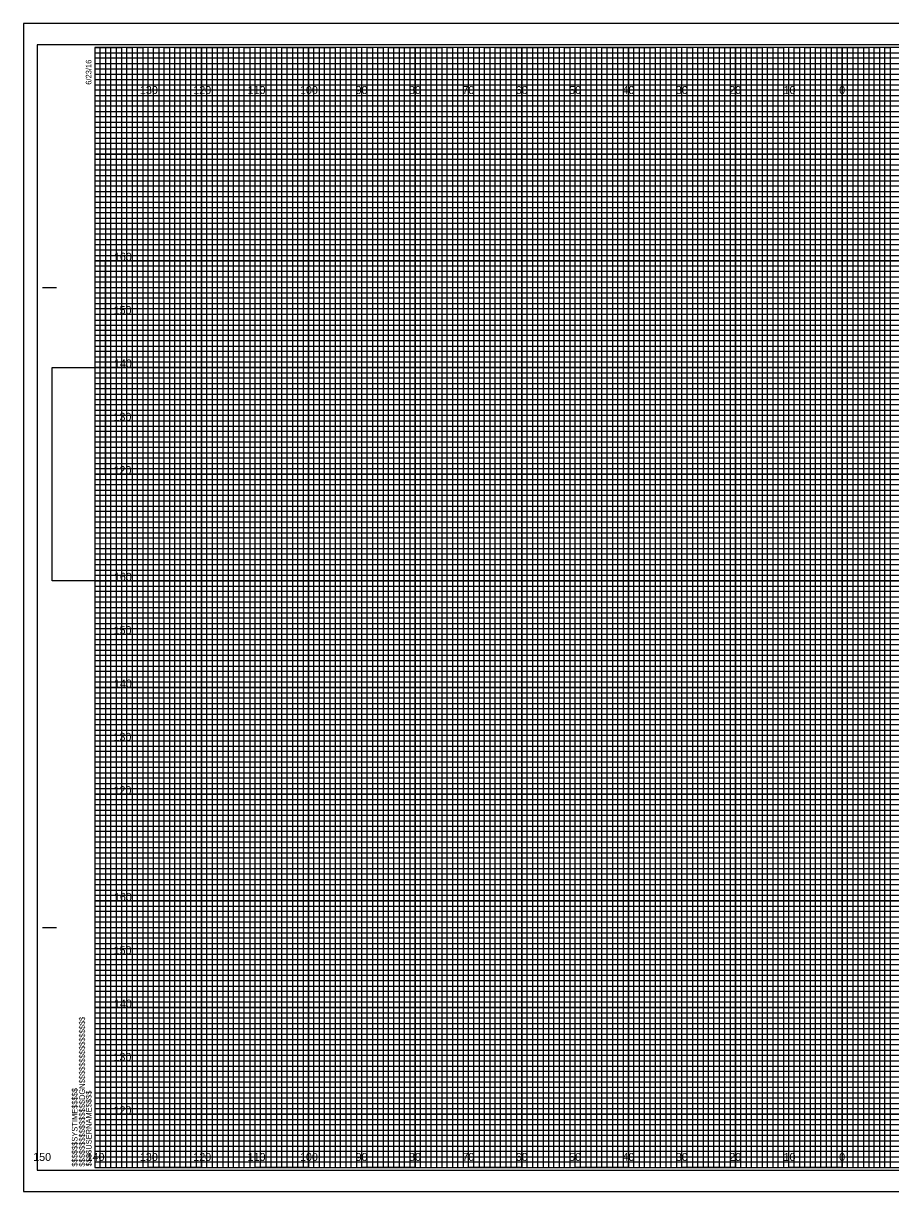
# Model space of a CAD drawing. Extents: x -13 to 323, y -5 to 3294.
# Drawn here: x -13.4 to 149.1, y 1095.5 to 1314.5 of the extents above; entities that cross this region are included whole.
import ezdxf

# ---------------------------------------------------------------- set-up
doc = ezdxf.new("R2010")
doc.units = 0
for name, color, linetype in [('Prop XS Elevation Labels', 7, 'Continuous'), ('Prop XS Offset Labels', 7, 'Continuous'), ('Scratch_Level_0', 7, 'Continuous'), ('Sheet Cross Section CELL', 7, 'Continuous'), ('Sheet Cross Section Grid Major CELL', 7, 'Continuous'), ('Sheet Cross Section Grid Middle CELL', 7, 'Continuous'), ('Sheet Cross Section Grid Minor 1 CELL', 7, 'Continuous'), ('Sheet Cross Section Grid Minor 2 CELL', 7, 'Continuous'), ('Sheet Cutting Line CELL', 7, 'Continuous'), ('Sheet DOT Grid CELL', 7, 'Continuous'), ('Sheet Plot Border Inside CELL', 7, 'Continuous'), ('Sheet Plot Border Outside CELL', 7, 'Continuous')]:
    doc.layers.add(name, color=color, linetype=linetype)

msp = doc.modelspace()

# ---------------------------------------------------------------- linework, layer by layer
at = {"layer": 'Scratch_Level_0'}
for points in [[(2, 1270), (310, 1270), (310, 1230), (2, 1230)], [(-8, 1250), (300, 1250), (300, 1210), (-8, 1210)], [(10, 1210), (310, 1210), (310, 1170), (10, 1170)], [(10, 1150), (310, 1150), (310, 1110), (10, 1110)]]:
    msp.add_lwpolyline(points, close=True, dxfattribs=at)
at = {"layer": 'Sheet Cross Section CELL'}
for p, q in [((-9.8, 1265), (-7.3, 1265)), ((-9.7, 1265), (-7.2, 1265)), ((-9.8, 1145), (-7.3, 1145)), ((-9.7, 1145), (-7.2, 1145)), ((0, 1100), (0, 1100)), ((0, 1100), (0, 1100)), ((0, 1100), (0, 1100)), ((0, 1100), (0, 1100)), ((0, 1100), (0, 1100)), ((0, 1100), (0, 1100)), ((0, 1100), (0, 1100))]:
    msp.add_line(p, q, dxfattribs=at)
msp.add_lwpolyline([(320, 1310), (0, 1310), (0, 1100), (320, 1100)], close=True, dxfattribs=at)
at = {"layer": 'Sheet Cross Section Grid Major CELL'}
for p, q in [((10, 1310), (0, 1310)), ((10, 1100), (10, 1310)), ((30, 1310), (20, 1310)), ((20, 1310), (20, 1100)), ((30, 1100), (30, 1310)), ((50, 1310), (40, 1310)), ((40, 1310), (40, 1100)), ((50, 1100), (50, 1310)), ((70, 1310), (60, 1310)), ((60, 1310), (60, 1100)), ((70, 1100), (70, 1310)), ((90, 1310), (80, 1310)), ((80, 1310), (80, 1100)), ((90, 1100), (90, 1310)), ((110, 1310), (100, 1310)), ((100, 1310), (100, 1100)), ((110, 1100), (110, 1310)), ((130, 1310), (120, 1310)), ((120, 1310), (120, 1100)), ((130, 1100), (130, 1310)), ((150, 1310), (140, 1310)), ((140, 1310), (140, 1100)), ((20, 1100), (10, 1100)), ((40, 1100), (30, 1100)), ((60, 1100), (50, 1100)), ((80, 1100), (70, 1100)), ((100, 1100), (90, 1100)), ((120, 1100), (110, 1100)), ((140, 1100), (130, 1100))]:
    msp.add_line(p, q, dxfattribs=at)
for points in [[(0, 1300), (320, 1300), (320, 1290), (0, 1290)], [(0, 1280), (320, 1280), (320, 1270), (0, 1270)], [(0, 1260), (320, 1260), (320, 1250), (0, 1250)], [(0, 1240), (320, 1240), (320, 1230), (0, 1230)], [(0, 1220), (320, 1220), (320, 1210), (0, 1210)], [(0, 1200), (320, 1200), (320, 1190), (0, 1190)], [(0, 1180), (320, 1180), (320, 1170), (0, 1170)], [(0, 1160), (320, 1160), (320, 1150), (0, 1150)], [(0, 1140), (320, 1140), (320, 1130), (0, 1130)], [(0, 1120), (320, 1120), (320, 1110), (0, 1110)]]:
    msp.add_lwpolyline(points, dxfattribs=at)
at = {"layer": 'Sheet Cross Section Grid Middle CELL'}
for points in [[(0, 1310), (5, 1310), (5, 1100), (15, 1100), (15, 1310), (25, 1310), (25, 1100), (35, 1100), (35, 1310), (45, 1310), (45, 1100), (55, 1100), (55, 1310), (65, 1310), (65, 1100), (75, 1100), (75, 1310), (85, 1310), (85, 1100), (95, 1100), (95, 1310), (105, 1310), (105, 1100), (115, 1100), (115, 1310), (125, 1310), (125, 1100), (135, 1100), (135, 1310), (145, 1310), (145, 1100), (155, 1100)], [(0, 1305), (275, 1305)], [(0, 1285), (320, 1285), (320, 1295), (0, 1295)], [(0, 1265), (320, 1265), (320, 1275), (0, 1275)], [(0, 1245), (320, 1245), (320, 1255), (0, 1255)], [(0, 1225), (320, 1225), (320, 1235), (0, 1235)], [(0, 1205), (320, 1205), (320, 1215), (0, 1215)], [(0, 1185), (320, 1185), (320, 1195), (0, 1195)], [(0, 1165), (320, 1165), (320, 1175), (0, 1175)], [(0, 1145), (320, 1145), (320, 1155), (0, 1155)], [(0, 1125), (320, 1125), (320, 1135), (0, 1135)], [(0, 1105), (320, 1105), (320, 1115), (0, 1115)]]:
    msp.add_lwpolyline(points, dxfattribs=at)
at = {"layer": 'Sheet Cross Section Grid Minor 1 CELL'}
for p, q in [((0, 1309), (260, 1309)), ((260, 1307.98), (0, 1307.98)), ((0, 1307.98), (0, 1307)), ((0, 1307), (260, 1307)), ((260, 1305.89), (0, 1305.89)), ((0, 1305.89), (0, 1304)), ((0, 1304), (320, 1304))]:
    msp.add_line(p, q, dxfattribs=at)
for points in [[(0, 1303), (270, 1303), (320, 1303), (320, 1302), (0, 1302)], [(0, 1301), (320, 1301), (320, 1299), (0, 1299)], [(0, 1298), (320, 1298), (320, 1297), (0, 1296.98)], [(0, 1296), (320, 1296), (320, 1294), (0, 1294)], [(0, 1293), (320, 1293), (320, 1292), (0, 1292)], [(0, 1291), (320, 1291), (320, 1289), (0, 1289)], [(0, 1288), (320, 1288), (320, 1287), (0, 1287)], [(0, 1286), (320, 1286), (320, 1284), (0, 1284)], [(0, 1283), (320, 1283), (320, 1282), (0, 1282)], [(0, 1281), (320, 1281), (320, 1279), (0, 1279)], [(0, 1278), (320, 1278), (320, 1277), (0, 1277)], [(0, 1276), (320, 1276), (320, 1273.95), (320, 1273), (320, 1272), (0, 1272)], [(0, 1274), (320, 1274), (320, 1273), (0, 1273)], [(0, 1271), (320, 1271), (320, 1269), (0, 1269.03)], [(0, 1269.03), (320, 1269), (320, 1268), (0, 1268)], [(0, 1267), (320, 1267), (320, 1266), (0, 1266)], [(0, 1264), (320, 1264), (320, 1263), (0, 1263)], [(0, 1262), (320, 1262), (320, 1261), (0, 1261)], [(-0.07, 1258.89), (320, 1258.89), (320, 1257.88), (-0.07, 1257.88)], [(0, 1257), (320, 1257), (320, 1256), (0, 1256)], [(0, 1254), (320, 1254), (320, 1253), (0, 1253)], [(0, 1252), (320, 1252), (320, 1251), (0, 1251)], [(0, 1249), (320, 1249), (320, 1248), (0, 1248)], [(0, 1247), (320, 1247), (320, 1246), (0, 1246)], [(0, 1244), (320, 1244), (320, 1243), (0, 1243)], [(0, 1242), (320, 1242), (320, 1241), (0, 1241)], [(0, 1239), (320, 1239), (319.99, 1237.98), (0, 1238)], [(0, 1237), (320, 1237), (320, 1236), (0, 1236)], [(0, 1234), (320, 1234), (320, 1233), (0, 1233)], [(0, 1232), (320, 1232), (320, 1231), (0, 1231)], [(0, 1229), (320, 1229), (320, 1228), (0, 1228)], [(0, 1227), (320, 1227), (320, 1226), (0, 1226)], [(0, 1224), (320, 1224), (320, 1223), (0, 1223)], [(0, 1222), (320, 1222), (320, 1221), (0, 1221)], [(0, 1219), (320, 1219), (320, 1218), (0, 1218)], [(0, 1216.99), (320.07, 1216.91), (320, 1216), (0, 1216)], [(0, 1214), (320, 1214), (320, 1213), (0, 1213)], [(0, 1212), (320, 1212), (320, 1211), (0, 1211)], [(0, 1209), (320, 1209), (320, 1208), (0, 1208)], [(0, 1207), (320, 1207), (320, 1206), (0, 1206)], [(0, 1204), (320, 1204), (320, 1203), (0, 1203)], [(0, 1202), (320, 1202), (320, 1201), (0, 1201)], [(0, 1199), (320, 1199), (320, 1198), (0, 1198)], [(0, 1197), (320, 1197), (320, 1196), (0, 1196)], [(0, 1194), (320, 1194), (320, 1193), (0, 1193)], [(0, 1192), (320, 1192), (320, 1191), (0, 1191)], [(0, 1189), (320, 1189), (320, 1188), (0, 1188)], [(0, 1187), (320, 1187), (320, 1186), (0, 1186)], [(0, 1184), (320, 1184), (320, 1183), (0, 1183)], [(0, 1182), (320, 1182), (320, 1181), (0, 1181)], [(0, 1179), (320, 1179), (319.99, 1177.98), (0, 1178)], [(0, 1177), (320, 1177), (320, 1176), (0, 1176)], [(0, 1174), (320, 1174), (320, 1173), (0, 1173)], [(0, 1172), (320, 1172), (320, 1171), (0, 1171)], [(0, 1169), (320, 1169), (320, 1168), (0, 1168)], [(0, 1167), (320, 1167), (320, 1166), (0, 1166)], [(0, 1164), (320, 1164), (320, 1163), (0, 1163)], [(0, 1162), (320, 1162), (320, 1161), (0, 1161)], [(0, 1159), (320, 1159), (320, 1158), (0, 1158)], [(0, 1156.99), (320.07, 1156.91), (320, 1156), (0, 1156)], [(0, 1154), (320, 1154), (320, 1153), (0, 1153)], [(0, 1152), (320, 1152), (320, 1151), (0, 1151)], [(0, 1149), (320, 1149), (320, 1148), (0, 1148)], [(0, 1147), (320, 1147), (320, 1146), (0, 1146)], [(0, 1144), (320, 1144), (320, 1143), (0, 1143)], [(0, 1142), (320, 1142), (320, 1141), (0, 1141)], [(0, 1139), (320, 1139), (320, 1138), (0, 1138)], [(0, 1137), (320, 1137), (320, 1136), (0, 1136)], [(0, 1134), (320, 1134), (320, 1133), (0, 1133)], [(0, 1132), (320, 1132), (320, 1131), (0, 1131)], [(0, 1129), (320, 1129), (320, 1128), (0, 1128)], [(0, 1127), (320, 1127), (320, 1126), (0, 1126)], [(0, 1124), (320, 1124), (320, 1123), (0, 1123)], [(0, 1122), (320, 1122), (320, 1121), (0, 1121)], [(0, 1119), (320, 1119), (320, 1118), (0, 1118)], [(0, 1117), (320, 1117), (320, 1116), (0, 1116)], [(0, 1114), (320, 1114), (320, 1113), (0, 1113)], [(0, 1112), (320, 1112), (320, 1111), (0, 1111)], [(0, 1109), (320, 1109), (320, 1108), (0, 1108)], [(0, 1107), (320, 1107), (320, 1106), (0, 1106)], [(0, 1104), (320, 1104), (320, 1103), (0, 1103)], [(0, 1102), (320, 1102), (320, 1101), (0, 1101)]]:
    msp.add_lwpolyline(points, dxfattribs=at)
at = {"layer": 'Sheet Cross Section Grid Minor 2 CELL'}
for points in [[(0, 1100), (1, 1100), (1, 1310), (2, 1310), (2, 1100)], [(2, 1100), (3, 1100), (3, 1310), (4, 1310), (4, 1100)], [(5, 1100), (6, 1100), (6, 1310), (7, 1310), (7, 1100)], [(7, 1100), (8, 1100), (8, 1310), (9, 1310), (9, 1100)], [(10, 1100), (11, 1100), (11, 1310), (12, 1310), (12, 1100)], [(12, 1100), (13, 1100), (13, 1310), (14, 1310), (14, 1100)], [(15, 1100), (16, 1100), (16, 1310), (17, 1310), (17, 1100)], [(17, 1100), (18, 1100), (18, 1310), (19, 1310), (19, 1100)], [(20, 1100), (21, 1100), (21, 1310), (22, 1310), (22, 1100)], [(22, 1100), (23, 1100), (23, 1310), (24, 1310), (24, 1100)], [(25, 1100), (26, 1100), (26, 1310), (27, 1310), (27, 1100)], [(27, 1100), (28, 1100), (28, 1310), (29, 1310), (29, 1100)], [(30, 1100), (31, 1100), (31, 1310), (32, 1310), (32, 1100)], [(32, 1100), (33, 1100), (33, 1310), (34, 1310), (34, 1100)], [(35, 1100), (36, 1100), (36, 1310), (37, 1310), (37, 1100)], [(37, 1100), (38, 1100), (38, 1310), (39, 1310), (39, 1100)], [(40, 1100), (41, 1100), (41, 1310), (42, 1310), (42, 1100)], [(42, 1100), (43, 1100), (43, 1310), (44, 1310), (44, 1100)], [(45, 1100), (46, 1100), (46, 1310), (47, 1310), (47, 1100)], [(47, 1100), (48, 1100), (48, 1310), (49, 1310), (49, 1100)], [(50, 1100), (51, 1100), (51, 1310), (52, 1310), (52, 1100)], [(52, 1100), (53, 1100), (53, 1310), (54, 1310), (54, 1100)], [(55, 1100), (56, 1100), (56, 1310), (57, 1310), (57, 1100)], [(57, 1100), (58, 1100), (58, 1310), (59, 1310), (59, 1100)], [(60, 1100), (61, 1100), (61, 1310), (62, 1310), (62, 1100)], [(62, 1100), (63, 1100), (63, 1310), (64, 1310), (64, 1100)], [(65, 1100), (66, 1100), (66, 1310), (67, 1310), (67, 1100)], [(67, 1100), (68, 1100), (68, 1310), (69, 1310), (69, 1100)], [(70, 1100), (71, 1100), (71, 1310), (72, 1310), (72, 1100)], [(72, 1100), (73, 1100), (73, 1310), (74, 1310), (74, 1100)], [(75, 1100), (76, 1100), (76, 1310), (77, 1310), (77, 1100)], [(77, 1100), (78, 1100), (78, 1310), (79, 1310), (79, 1100)], [(80, 1100), (81, 1100), (81, 1310), (82, 1310), (82, 1100)], [(82, 1100), (83, 1100), (83, 1310), (84, 1310), (84, 1100)], [(85, 1100), (86, 1100), (86, 1310), (87, 1310), (87, 1100)], [(87, 1100), (88, 1100), (88, 1310), (89, 1310), (89, 1100)], [(90, 1100), (91, 1100), (91, 1310), (92, 1310), (92, 1100)], [(92, 1100), (93, 1100), (93, 1310), (94, 1310), (94, 1100)], [(95, 1100), (96, 1100), (96, 1310), (97, 1310), (97, 1100)], [(97, 1100), (98, 1100), (98, 1310), (99, 1310), (99, 1100)], [(100, 1100), (101, 1100), (101, 1310), (102, 1310), (102, 1100)], [(102, 1100), (103, 1100), (103, 1310), (104, 1310), (104, 1100)], [(105, 1100), (106, 1100), (106, 1310), (107, 1310), (107, 1100)], [(107, 1100), (108, 1100), (108, 1310), (109, 1310), (109, 1100)], [(110, 1100), (111, 1100), (111, 1310), (112, 1310), (112, 1100)], [(112, 1100), (113, 1100), (113, 1310), (114, 1310), (114, 1100)], [(115, 1100), (116, 1100), (116, 1310), (117, 1310), (117, 1100)], [(117, 1100), (118, 1100), (118, 1310), (119, 1310), (119, 1100)], [(120, 1100), (121, 1100), (121, 1310), (122, 1310), (122, 1100)], [(122, 1100), (123, 1100), (123, 1310), (124, 1310), (124, 1100)], [(125, 1100), (126, 1100), (126, 1310), (127, 1310), (127, 1100)], [(127, 1100), (128, 1100), (128, 1310), (129, 1310), (129, 1100)], [(130, 1100), (131, 1100), (131, 1310), (132, 1310), (132, 1100)], [(132, 1100), (133, 1100), (133, 1310), (134, 1310), (134, 1100)], [(135, 1100), (136, 1100), (136, 1310), (137, 1310), (137, 1100)], [(137, 1100), (138, 1100), (138, 1310), (139, 1310), (139, 1100)], [(140, 1100), (141, 1100), (141, 1310), (142, 1310), (142, 1100)], [(142, 1100), (143, 1100), (143, 1310), (144, 1310), (144, 1100)], [(145, 1100), (146, 1100), (146, 1310), (147, 1310), (147, 1100)], [(147, 1100), (148, 1100), (148, 1310), (149, 1310), (149, 1100)]]:
    msp.add_lwpolyline(points, dxfattribs=at)
at = {"layer": 'Sheet Cutting Line CELL'}
for p, q in [((323.3, 1314.5), (-13.4, 1314.5)), ((-13.4, 1314.5), (-13.4, 1095.5)), ((-13.4, 1095.5), (323.3, 1095.5))]:
    msp.add_line(p, q, dxfattribs=at)
at = {"layer": 'Sheet DOT Grid CELL'}
for p, q in [((10, 1100), (10, 1310)), ((20, 1100), (20, 1310)), ((30, 1100), (30, 1310)), ((40, 1100), (40, 1310)), ((50, 1100), (50, 1310)), ((60, 1100), (60, 1310)), ((70, 1100), (70, 1310)), ((80, 1100), (80, 1310)), ((90, 1100), (90, 1310)), ((100, 1100), (100, 1310)), ((110, 1100), (110, 1310)), ((120, 1100), (120, 1310)), ((130, 1100), (130, 1310)), ((140, 1100), (140, 1310)), ((0, 1300), (320, 1300)), ((0, 1290), (320, 1290)), ((0, 1280), (320, 1280)), ((0, 1270), (320, 1270)), ((0, 1260), (320, 1260)), ((0, 1250), (320, 1250)), ((0, 1240), (320, 1240)), ((0, 1230), (320, 1230)), ((0, 1220), (320, 1220)), ((0, 1210), (320, 1210)), ((0, 1200), (320, 1200)), ((0, 1190), (320, 1190)), ((0, 1180), (320, 1180)), ((0, 1170), (320, 1170)), ((0, 1160), (320, 1160)), ((0, 1150), (320, 1150)), ((0, 1140), (320, 1140)), ((0, 1130), (320, 1130)), ((0, 1120), (320, 1120)), ((0, 1110), (320, 1110))]:
    msp.add_line(p, q, dxfattribs=at)
at = {"layer": 'Sheet Plot Border Inside CELL'}
msp.add_lwpolyline([(-10.8, 1099.5), (322.4, 1099.5), (322.4, 1310.5), (-10.8, 1310.5)], close=True, dxfattribs=at)
at = {"layer": 'Sheet Plot Border Outside CELL'}
msp.add_lwpolyline([(-13.4, 1095.5), (323.3, 1095.5), (323.3, 1314.5), (-13.4, 1314.5)], close=True, dxfattribs=at)

# ---------------------------------------------------------------- texts
at = {"layer": 'Prop XS Elevation Labels'}
for s, p in [('160', (3.57, 1270)), ('150', (3.52, 1260)), ('140', (3.57, 1250)), ('130', (3.49, 1240)), ('120', (3.5, 1230)), ('160', (3.57, 1210)), ('150', (3.52, 1200)), ('140', (3.57, 1190)), ('130', (3.49, 1180)), ('120', (3.5, 1170)), ('160', (3.57, 1150)), ('150', (3.52, 1140)), ('140', (3.57, 1130)), ('130', (3.49, 1120)), ('120', (3.5, 1110))]:
    msp.add_text(s, height=1.5, dxfattribs=at).set_placement(p)
at = {"layer": 'Prop XS Offset Labels'}
for s, p in [('130', (8.44, 1301.25)), ('120', (18.44, 1301.25)), ('110', (28.62, 1301.25)), ('100', (38.44, 1301.25)), ('90', (48.86, 1301.25)), ('80', (58.86, 1301.25)), ('70', (68.86, 1301.25)), ('60', (78.86, 1301.25)), ('50', (88.86, 1301.25)), ('40', (98.86, 1301.25)), ('30', (108.86, 1301.25)), ('20', (118.86, 1301.25)), ('10', (129.04, 1301.25)), ('0', (139.45, 1301.25)), ('0', (139.45, 1301.25)), ('150', (-11.56, 1101.25)), ('140', (-1.56, 1101.25)), ('130', (8.44, 1101.25)), ('120', (18.44, 1101.25)), ('110', (28.62, 1101.25)), ('100', (38.44, 1101.25)), ('90', (48.86, 1101.25)), ('80', (58.86, 1101.25)), ('70', (68.86, 1101.25)), ('60', (78.86, 1101.25)), ('50', (88.86, 1101.25)), ('40', (98.86, 1101.25)), ('30', (108.86, 1101.25)), ('20', (118.86, 1101.25)), ('10', (129.04, 1101.25)), ('0', (139.45, 1101.25)), ('0', (139.45, 1101.25))]:
    msp.add_text(s, height=1.5, dxfattribs=at).set_placement(p)
at = {"layer": 'Sheet Cross Section CELL'}
for s, p in [('6/23/16', (-0.65, 1303)), ('$$$$$$$$$$$$$$$$DGN$$$$$$$$$$$$$$$$', (-1.88, 1100.18)), ('$$$$$$SYSTIME$$$$$', (-3.26, 1100.18)), ('$$$$USERNAME$$$$', (-0.62, 1100.23))]:
    msp.add_text(s, height=1.05, rotation=90, dxfattribs=at).set_placement(p)

doc.saveas('drawing.dxf')
